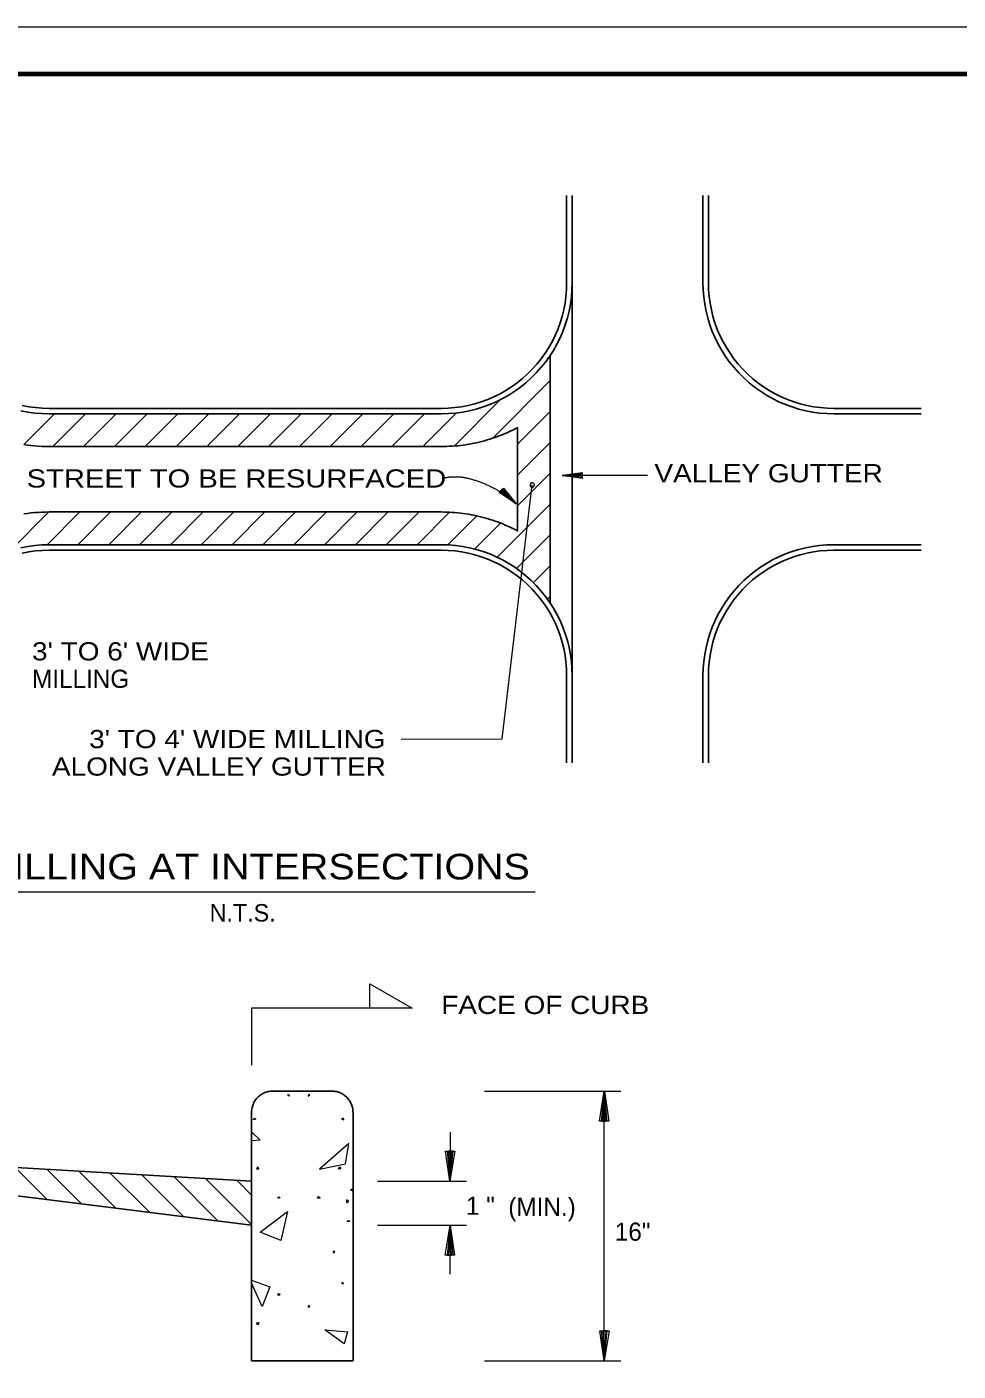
# Model space of a CAD drawing. Extents: x 44.6 to 61.6, y -38.7 to -27.7.
# Drawn here: x 50.34 to 54.61, y -33.85 to -27.69 of the extents above; entities that cross this region are included whole.
import ezdxf

# ---------------------------------------------------------------- set-up
doc = ezdxf.new("R2010")
doc.units = 0
doc.header["$LTSCALE"] = 0.025
doc.layers.add('10', color=7, linetype='Continuous')
for name, color, linetype, lineweight in [('6', 7, 'Continuous', 13), ('60', 7, 'Continuous', 13), ('8', 7, 'Continuous', 13), ('9', 7, 'Continuous', 13)]:
    doc.layers.add(name, color=color, linetype=linetype, lineweight=lineweight)

msp = doc.modelspace()

# ---------------------------------------------------------------- linework, layer by layer
at = {"layer": '6', "lineweight": 25}
for p, q in [((52.8405, -30.66542), (52.8405, -28.86542)), ((52.7405, -30.33375), (52.7405, -29.19707))]:
    msp.add_line(p, q, dxfattribs=at)
at = {"layer": '6'}
for p, q in [((52.7405, -29.31338), (52.47658, -29.57729)), ((52.29935, -29.6131), (52.51196, -29.40049)), ((50.32615, -29.60641), (50.46714, -29.46542)), ((50.60856, -29.46542), (50.45856, -29.61542)), ((50.59998, -29.61542), (50.74998, -29.46542)), ((50.89141, -29.46542), (50.74141, -29.61542)), ((50.88282, -29.61542), (51.03282, -29.46542)), ((51.17425, -29.46542), (51.02425, -29.61542)), ((51.16567, -29.61542), (51.31567, -29.46542)), ((51.45708, -29.46542), (51.30708, -29.61542)), ((51.44851, -29.61542), (51.59851, -29.46542)), ((51.73993, -29.46542), (51.58993, -29.61542)), ((51.73135, -29.61542), (51.88135, -29.46542)), ((52.02277, -29.46542), (51.87277, -29.61542)), ((52.0142, -29.61542), (52.1642, -29.46542)), ((52.30961, -29.46142), (52.15561, -29.61542)), ((52.5905, -29.60479), (52.7405, -29.45479)), ((52.7405, -29.59622), (52.5905, -29.74622)), ((52.5905, -29.88764), (52.7405, -29.73764)), ((53.18669, -29.74781), (52.79539, -29.74781)), ((52.7405, -29.87906), (52.4967, -30.12286)), ((50.44172, -29.91509), (50.26455, -30.09226)), ((50.43275, -30.06549), (50.58282, -29.91542)), ((50.72425, -29.91542), (50.57425, -30.06542)), ((50.71567, -30.06542), (50.86567, -29.91542)), ((51.00708, -29.91542), (50.85708, -30.06542)), ((50.99851, -30.06542), (51.14851, -29.91542)), ((51.28993, -29.91542), (51.13993, -30.06542)), ((51.28135, -30.06542), (51.43135, -29.91542)), ((51.57277, -29.91542), (51.42277, -30.06542)), ((51.5642, -30.06542), (51.7142, -29.91542)), ((51.85561, -29.91542), (51.70561, -30.06542)), ((51.84704, -30.06542), (51.99704, -29.91542)), ((52.13846, -29.91542), (51.98846, -30.06542)), ((52.12989, -30.06542), (52.2789, -29.9164)), ((52.4034, -29.93332), (52.27055, -30.06617)), ((52.39301, -30.08512), (52.5119, -29.96624)), ((52.58606, -30.17492), (52.7405, -30.02048)), ((52.7405, -30.16191), (52.663, -30.2394)), ((52.72807, -30.31575), (52.7405, -30.30332)), ((52.43949, -32.56991), (53.06341, -32.56991)), ((52.98778, -33.80639), (52.98778, -32.56991)), ((52.28068, -32.75897), (52.28068, -32.98332)), ((50.2867, -32.9203), (50.43543, -33.06778)), ((50.59172, -33.08795), (50.43291, -32.92914)), ((50.57786, -32.9367), (50.74801, -33.10684)), ((50.9043, -33.12701), (50.7228, -32.94551)), ((50.86776, -32.95434), (51.06059, -33.14593)), ((51.21689, -33.16609), (51.01397, -32.96191)), ((51.15891, -32.97072), (51.37193, -33.18374)), ((51.37066, -33.04634), (51.30386, -32.97955)), ((51.94793, -32.98332), (52.3563, -32.98332)), ((51.94793, -33.18499), (52.3563, -33.18499)), ((52.28068, -33.40934), (52.28068, -33.18499)), ((52.43949, -33.80639), (53.06341, -33.80639))]:
    msp.add_line(p, q, dxfattribs=at)
at = {"layer": '6', "lineweight": 25}
for points in [[(52.8405, -28.46542), (52.8405, -28.86542), (52.83961, -28.8979), (52.83698, -28.93028), (52.83259, -28.96248), (52.82647, -28.9944), (52.81862, -29.02593), (52.80909, -29.057), (52.79789, -29.0875), (52.78504, -29.11734), (52.7706, -29.14646), (52.75461, -29.17475), (52.73711, -29.20212), (52.71816, -29.22852), (52.69779, -29.25384), (52.67609, -29.27803), (52.65311, -29.30101), (52.62893, -29.32271), (52.6036, -29.34307), (52.57721, -29.36203), (52.54983, -29.37953), (52.52154, -29.39552), (52.49244, -29.40996), (52.46258, -29.4228), (52.43208, -29.43401), (52.40102, -29.44354), (52.36948, -29.45139), (52.33757, -29.45751), (52.30537, -29.4619), (52.27298, -29.46454), (52.2405, -29.46542), (52.2405, -29.46542), (50.44203, -29.46542), (50.40955, -29.46453), (50.37717, -29.4619), (50.34497, -29.45751), (50.31305, -29.45139)], [(50.31843, -29.42697), (50.34901, -29.43284), (50.37986, -29.43704), (50.4109, -29.43957), (50.44203, -29.44042), (50.44203, -29.44042), (52.2405, -29.44042), (52.27163, -29.43957), (52.30267, -29.43704), (52.33352, -29.43284), (52.3641, -29.42697), (52.39432, -29.41946), (52.42409, -29.41031), (52.45332, -29.39957), (52.48194, -29.38727), (52.50983, -29.37344), (52.53694, -29.3581), (52.56318, -29.34133), (52.58847, -29.32317), (52.61275, -29.30366), (52.63593, -29.28286), (52.65795, -29.26084), (52.67874, -29.23767), (52.69825, -29.2134), (52.71642, -29.18809), (52.73319, -29.16186), (52.74852, -29.13475), (52.76235, -29.10685), (52.77466, -29.07825), (52.7854, -29.04901), (52.79454, -29.01925), (52.80205, -28.98902), (52.80793, -28.95844), (52.81213, -28.92758), (52.81466, -28.89654), (52.8155, -28.86542), (52.8155, -28.86542), (52.8155, -28.46542)], [(54.4405, -29.46542), (54.0405, -29.46542), (54.00801, -29.46453), (53.97563, -29.4619), (53.94343, -29.45751), (53.91152, -29.45139), (53.87998, -29.44354), (53.84892, -29.43401), (53.81842, -29.4228), (53.78856, -29.40996), (53.75946, -29.39552), (53.73117, -29.37953), (53.70379, -29.36203), (53.6774, -29.34307), (53.65206, -29.32271), (53.62787, -29.30101), (53.60491, -29.27803), (53.5832, -29.25384), (53.56284, -29.22852), (53.54389, -29.20212), (53.52639, -29.17475), (53.5104, -29.14646), (53.49596, -29.11735), (53.48311, -29.0875), (53.47191, -29.057), (53.46236, -29.02594), (53.45453, -28.9944), (53.44841, -28.96249), (53.44402, -28.93029), (53.44138, -28.8979), (53.4405, -28.86542), (53.4405, -28.86542), (53.4405, -28.46542)], [(53.4655, -28.46542), (53.4655, -28.86542), (53.46634, -28.89654), (53.46886, -28.92758), (53.47307, -28.95844), (53.47894, -28.98902), (53.48646, -29.01924), (53.49559, -29.04901), (53.50633, -29.07824), (53.51865, -29.10685), (53.53248, -29.13475), (53.5478, -29.16185), (53.56457, -29.18809), (53.58275, -29.2134), (53.60225, -29.23767), (53.62305, -29.26084), (53.64507, -29.28286), (53.66825, -29.30366), (53.69252, -29.32317), (53.71781, -29.34133), (53.74405, -29.3581), (53.77117, -29.37344), (53.79906, -29.38727), (53.82767, -29.39957), (53.8569, -29.41031), (53.88667, -29.41946), (53.9169, -29.42697), (53.94748, -29.43284), (53.97833, -29.43704), (54.00936, -29.43957), (54.0405, -29.44042), (54.0405, -29.44042), (54.4405, -29.44042)], [(50.326, -29.60639), (50.34247, -29.60878), (50.35899, -29.6108), (50.37555, -29.61247), (50.39215, -29.61376), (50.40876, -29.61468), (50.42539, -29.61523), (50.44203, -29.61542), (52.2405, -29.61542), (52.25305, -29.61531), (52.2656, -29.61499), (52.27816, -29.61447), (52.29069, -29.61373), (52.30321, -29.61279), (52.31571, -29.61164), (52.3282, -29.61027), (52.34065, -29.6087), (52.35308, -29.60692), (52.36548, -29.60493), (52.37784, -29.60273), (52.39017, -29.60033), (52.40245, -29.59772), (52.41469, -29.59491), (52.42687, -29.59189), (52.43901, -29.58867), (52.45109, -29.58524), (52.46311, -29.58161), (52.47507, -29.57779), (52.48696, -29.57376), (52.49879, -29.56954), (52.51054, -29.56511), (52.52222, -29.5605), (52.53381, -29.55568), (52.54532, -29.55068), (52.55676, -29.54548), (52.56809, -29.54008), (52.57934, -29.53451), (52.5905, -29.52874), (52.5905, -29.52874), (52.5905, -30.00209), (52.57934, -29.99632), (52.56809, -29.99074), (52.55675, -29.98535), (52.54532, -29.98016), (52.53381, -29.97515), (52.52222, -29.97033), (52.51054, -29.96572), (52.49878, -29.96129), (52.48696, -29.95707), (52.47507, -29.95304), (52.46311, -29.94922), (52.45109, -29.94558), (52.43901, -29.94217), (52.42687, -29.93894), (52.41469, -29.93593), (52.40245, -29.93311), (52.39017, -29.9305), (52.37784, -29.92809), (52.36548, -29.92591), (52.35308, -29.92392), (52.34065, -29.92214), (52.3282, -29.92056), (52.31571, -29.9192), (52.30321, -29.91804), (52.29069, -29.91709), (52.27816, -29.91636), (52.2656, -29.91583), (52.25305, -29.91552), (52.2405, -29.91542), (50.44203, -29.91542), (50.4254, -29.9156), (50.40876, -29.91616), (50.39215, -29.91707), (50.37555, -29.91836), (50.35899, -29.92003), (50.34247, -29.92205), (50.326, -29.92445)], [(50.31305, -30.07945), (50.34496, -30.07332), (50.37716, -30.06894), (50.40955, -30.06629), (50.44203, -30.06542), (52.2405, -30.06542), (52.27298, -30.06629), (52.30537, -30.06893), (52.33757, -30.07332), (52.36948, -30.07944), (52.40102, -30.08728), (52.43208, -30.09682), (52.46258, -30.10803), (52.49244, -30.12086), (52.52154, -30.13531), (52.54983, -30.1513), (52.57721, -30.1688), (52.6036, -30.18776), (52.62893, -30.20811), (52.65311, -30.22982), (52.67609, -30.25279), (52.69779, -30.27698), (52.71816, -30.30231), (52.73711, -30.32871), (52.75461, -30.35608), (52.7706, -30.38437), (52.78504, -30.41348), (52.79789, -30.44333), (52.80909, -30.47383), (52.81862, -30.5049), (52.82647, -30.53644), (52.83259, -30.56834), (52.83698, -30.60054), (52.83961, -30.63294), (52.8405, -30.66542), (52.8405, -30.66542), (52.8405, -31.06542)], [(53.4405, -31.06542), (53.4405, -30.66542), (53.44138, -30.63293), (53.44402, -30.60054), (53.44841, -30.56834), (53.45453, -30.53644), (53.46236, -30.5049), (53.47191, -30.47383), (53.48311, -30.44333), (53.49596, -30.41348), (53.5104, -30.38437), (53.52639, -30.35608), (53.54389, -30.3287), (53.56284, -30.30231), (53.5832, -30.27698), (53.60491, -30.25279), (53.62787, -30.22982), (53.65206, -30.20811), (53.6774, -30.18776), (53.70379, -30.1688), (53.73117, -30.1513), (53.75946, -30.13531), (53.78856, -30.12087), (53.81842, -30.10803), (53.84892, -30.09682), (53.87998, -30.08728), (53.91152, -30.07945), (53.94343, -30.07332), (53.97563, -30.06894), (54.00802, -30.06629), (54.0405, -30.06542), (54.4405, -30.06542)], [(52.8155, -31.06542), (52.8155, -30.66542), (52.81466, -30.63428), (52.81213, -30.60325), (52.80793, -30.57239), (52.80205, -30.5418), (52.79454, -30.51158), (52.7854, -30.48181), (52.77466, -30.45258), (52.76235, -30.42398), (52.74852, -30.39608), (52.73319, -30.36897), (52.71642, -30.34273), (52.69825, -30.31744), (52.67874, -30.29317), (52.65795, -30.26999), (52.63593, -30.24797), (52.61275, -30.22718), (52.58847, -30.20767), (52.56318, -30.1895), (52.53694, -30.17272), (52.50983, -30.1574), (52.48194, -30.14356), (52.45332, -30.13125), (52.42409, -30.12052), (52.39432, -30.11137), (52.3641, -30.10386), (52.33352, -30.09799), (52.30267, -30.09379), (52.27163, -30.09126), (52.2405, -30.09042), (52.2405, -30.09042), (50.44203, -30.09042), (50.41091, -30.09126), (50.37986, -30.09378), (50.34901, -30.09799), (50.31843, -30.10385)], [(54.4405, -30.09042), (54.0405, -30.09042), (54.00936, -30.09126), (53.97833, -30.09378), (53.94747, -30.09799), (53.91689, -30.10385), (53.88667, -30.11137), (53.8569, -30.12051), (53.82767, -30.13125), (53.79906, -30.14356), (53.77117, -30.1574), (53.74405, -30.17272), (53.71781, -30.18949), (53.69252, -30.20767), (53.66825, -30.22718), (53.64507, -30.24797), (53.62305, -30.26999), (53.60225, -30.29317), (53.58275, -30.31744), (53.56457, -30.34273), (53.5478, -30.36897), (53.53248, -30.39608), (53.51865, -30.42398), (53.50633, -30.45258), (53.49559, -30.48182), (53.48646, -30.51158), (53.47894, -30.54181), (53.47307, -30.5724), (53.46886, -30.60325), (53.46634, -30.63429), (53.4655, -30.66542), (53.4655, -31.06542)], [(51.7387, -32.56991), (51.46772, -32.56991), (51.46768, -32.56984), (51.46244, -32.56999), (51.45721, -32.57042), (51.45202, -32.57113), (51.44686, -32.57211), (51.44178, -32.57337), (51.43677, -32.57492), (51.43184, -32.57672), (51.42703, -32.57879), (51.42233, -32.58113), (51.41777, -32.58371), (51.41335, -32.58653), (51.40909, -32.58958), (51.40501, -32.59287), (51.4011, -32.59638), (51.3974, -32.60008), (51.3939, -32.60398), (51.39061, -32.60806), (51.38755, -32.61232), (51.38473, -32.61674), (51.38216, -32.6213), (51.37982, -32.626), (51.37775, -32.63082), (51.37595, -32.63574), (51.37441, -32.64075), (51.37314, -32.64583), (51.37216, -32.65099), (51.37145, -32.65618), (51.37102, -32.66141), (51.37087, -32.66665), (51.37087, -32.66665), (51.37066, -32.66697), (51.37066, -33.80639), (51.83576, -33.80639), (51.83576, -32.66697), (51.83552, -32.66665), (51.83537, -32.66141), (51.83495, -32.65618), (51.83424, -32.65099), (51.83325, -32.64583), (51.83199, -32.64075), (51.83045, -32.63574), (51.82865, -32.63082), (51.82657, -32.626), (51.82424, -32.6213), (51.82166, -32.61674), (51.81883, -32.61232), (51.81578, -32.60806), (51.81249, -32.60398), (51.80899, -32.60008), (51.80528, -32.59638), (51.80139, -32.59287), (51.7973, -32.58958), (51.79304, -32.58653), (51.78862, -32.58371), (51.78406, -32.58113), (51.77936, -32.57879), (51.77454, -32.57672), (51.76962, -32.57492), (51.76461, -32.57337), (51.75952, -32.57211), (51.75437, -32.57113), (51.74919, -32.57042), (51.74396, -32.56999), (51.73872, -32.56984), (51.73872, -32.56984)]]:
    msp.add_lwpolyline(points, dxfattribs=at)
at = {"layer": '6'}
for points in [[(52.24596, -29.7608), (52.24795, -29.76031), (52.24994, -29.75984), (52.25194, -29.7594), (52.25394, -29.75896), (52.25594, -29.75854), (52.25794, -29.75815), (52.25995, -29.75776), (52.26196, -29.7574), (52.26398, -29.75704), (52.26599, -29.75671), (52.26801, -29.7564), (52.27003, -29.75609), (52.27206, -29.75581), (52.27409, -29.75555), (52.27611, -29.7553), (52.27815, -29.75507), (52.28019, -29.75485), (52.28222, -29.75466), (52.28426, -29.75448), (52.28629, -29.75431), (52.28833, -29.75417), (52.29037, -29.75404), (52.29242, -29.75393), (52.29446, -29.75383), (52.2965, -29.75376), (52.29855, -29.7537), (52.30059, -29.75366), (52.30264, -29.75362), (52.30468, -29.75362), (52.30673, -29.75362), (52.30877, -29.75366), (52.31081, -29.7537), (52.31286, -29.75376), (52.31491, -29.75383), (52.31695, -29.75393), (52.31899, -29.75404), (52.32103, -29.75417), (52.32307, -29.75431), (52.3251, -29.75448), (52.32715, -29.75466), (52.32918, -29.75485), (52.33122, -29.75507), (52.33325, -29.7553), (52.33527, -29.75555), (52.3373, -29.75581), (52.33933, -29.75609), (52.34135, -29.7564), (52.34338, -29.75671), (52.34539, -29.75704), (52.34741, -29.7574), (52.34942, -29.75776), (52.35143, -29.75815), (52.35343, -29.75854), (52.35543, -29.75896), (52.35743, -29.7594), (52.35943, -29.75984), (52.36142, -29.76031), (52.36341, -29.7608), (52.36761, -29.76186), (52.37182, -29.76297), (52.37602, -29.7641), (52.3802, -29.76527), (52.38437, -29.76648), (52.38854, -29.76772), (52.3927, -29.76899), (52.39684, -29.7703), (52.40098, -29.77165), (52.40509, -29.77302), (52.40921, -29.77444), (52.4133, -29.77589), (52.41739, -29.77736), (52.42146, -29.77889), (52.42552, -29.78044), (52.42957, -29.78202), (52.4336, -29.78365), (52.43762, -29.78529), (52.44162, -29.78698), (52.44561, -29.7887), (52.44959, -29.79046), (52.45355, -29.79224), (52.4575, -29.79406), (52.46144, -29.79592), (52.46535, -29.7978), (52.46925, -29.79972), (52.47314, -29.80167), (52.477, -29.80366), (52.48085, -29.80567), (52.48469, -29.80772), (52.4885, -29.80979), (52.4923, -29.81191), (52.49608, -29.81405), (52.49984, -29.81623), (52.50358, -29.81844), (52.50731, -29.82068), (52.51102, -29.82295), (52.51471, -29.82524), (52.51837, -29.82757), (52.52202, -29.82994), (52.52565, -29.83233), (52.52926, -29.83475)], [(52.05694, -30.95607), (52.52047, -30.95509), (52.65744, -29.79157)], [(52.52926, -29.83475), (52.53284, -29.83721), (52.53641, -29.83969), (52.53996, -29.84221), (52.54348, -29.84475), (52.54698, -29.84732), (52.55047, -29.84992), (52.55393, -29.85255), (52.55736, -29.85521), (52.56078, -29.8579), (52.56417, -29.86061), (52.56754, -29.86336), (52.57089, -29.86614), (52.57421, -29.86894), (52.57751, -29.87176), (52.58078, -29.87462), (52.58403, -29.87751)], [(52.10674, -32.19016), (51.37066, -32.19016), (51.37066, -32.4507)], [(51.37066, -32.75645), (51.40974, -32.79426), (51.37066, -32.79805)], [(51.37066, -33.43707), (51.45384, -33.46732), (51.41982, -33.55807), (51.37066, -33.44968)]]:
    msp.add_lwpolyline(points, dxfattribs=at)
for points in [[(52.66083, -29.78217), (52.65979, -29.78185), (52.65873, -29.78166), (52.65765, -29.78157), (52.65656, -29.78161), (52.6555, -29.78176), (52.65445, -29.78203), (52.65343, -29.78241), (52.65247, -29.7829), (52.65155, -29.78349), (52.65072, -29.78417), (52.64996, -29.78494), (52.64928, -29.78578), (52.64871, -29.7867), (52.64823, -29.78768), (52.64786, -29.7887), (52.6476, -29.78975), (52.64747, -29.79082), (52.64744, -29.79191), (52.64753, -29.79298), (52.64775, -29.79404), (52.64807, -29.79507), (52.6485, -29.79606), (52.64904, -29.79701), (52.64968, -29.79789), (52.65041, -29.79869), (52.65122, -29.79941), (52.6521, -29.80003), (52.65304, -29.80055), (52.65404, -29.80098), (52.65404, -29.80098), (52.65508, -29.80129), (52.65615, -29.80149), (52.65722, -29.80157), (52.6583, -29.80153), (52.65937, -29.80139), (52.66043, -29.80111), (52.66144, -29.80074), (52.66241, -29.80025), (52.66331, -29.79966), (52.66416, -29.79898), (52.66492, -29.79821), (52.66559, -29.79736), (52.66617, -29.79645), (52.66665, -29.79547), (52.66701, -29.79446), (52.66727, -29.7934), (52.66741, -29.79232), (52.66743, -29.79124), (52.66733, -29.79017), (52.66712, -29.7891), (52.6668, -29.78807), (52.66636, -29.78708), (52.66583, -29.78614), (52.6652, -29.78526), (52.66447, -29.78446), (52.66366, -29.78374), (52.66277, -29.78311), (52.66183, -29.78259), (52.66083, -29.78217)], [(52.10674, -32.19016), (51.9124, -32.19016), (51.9124, -32.07868)], [(51.53578, -32.58755), (51.54207, -32.58503), (51.54334, -32.59259)], [(51.63786, -32.58755), (51.63157, -32.58503), (51.6303, -32.59259)], [(51.37949, -32.70099), (51.38326, -32.69343), (51.39082, -32.69722)], [(51.79416, -32.70099), (51.79039, -32.69343), (51.78282, -32.69722)], [(51.68199, -32.92786), (51.80172, -32.90393), (51.81684, -32.81066)], [(51.39334, -32.92661), (51.4047, -32.92786), (51.39966, -32.91778)], [(51.7803, -32.92661), (51.76895, -32.92786), (51.77399, -32.91778)], [(51.83197, -33.02618), (51.83072, -33.01861), (51.82441, -33.02366)], [(51.48914, -33.06022), (51.49545, -33.05518), (51.50174, -33.05895)], [(51.68451, -33.06022), (51.6782, -33.05518), (51.67191, -33.05895)], [(51.80551, -33.08164), (51.81684, -33.07534), (51.80551, -33.06903)], [(51.40974, -33.21651), (51.53578, -33.12197), (51.50426, -33.25557)], [(51.82064, -33.16609), (51.81307, -33.16482), (51.80676, -33.16734)], [(51.75257, -33.30599), (51.74501, -33.30474), (51.74626, -33.3123)], [(51.79291, -33.45347), (51.78911, -33.44716), (51.78282, -33.45095)], [(51.48914, -33.50009), (51.49545, -33.50514), (51.50174, -33.50136)], [(51.63786, -33.55555), (51.63157, -33.55303), (51.6303, -33.56059)], [(51.39334, -33.63245), (51.4047, -33.63118), (51.39966, -33.64253)], [(51.7072, -33.66395), (51.81055, -33.67403), (51.79543, -33.72824)]]:
    msp.add_lwpolyline(points, close=True, dxfattribs=at)
at = {"layer": '6', "lineweight": 25}
msp.add_lwpolyline([(51.37066, -32.98332), (48.36457, -32.80939), (51.37066, -33.18499)], close=True, dxfattribs=at)
at = {"layer": '60'}
msp.add_lwpolyline([(61.57033, -38.69864), (44.55984, -38.69864), (44.55984, -27.69184), (61.57033, -27.69184)], close=True, dxfattribs=at)
at = {"layer": '60', "lineweight": 70}
msp.add_lwpolyline([(60.8892, -27.90872), (44.82119, -27.90872), (44.82119, -38.46427), (60.8892, -38.46427)], close=True, dxfattribs=at)
at = {"layer": '8'}
msp.add_line((50.11106, -31.65631), (52.67071, -31.65631), dxfattribs=at)
at = {"layer": '9'}
for points in [[(52.8869, -29.73867), (52.79539, -29.74781), (52.8869, -29.74781), (52.8869, -29.75239), (52.79539, -29.74781), (52.8869, -29.75696), (52.8869, -29.74324), (52.79997, -29.74781)], [(52.79584, -29.74722), (52.88697, -29.73412), (52.88697, -29.76246), (52.79553, -29.74754)], [(52.58329, -29.87765), (52.50665, -29.82665), (52.52554, -29.80553), (52.58374, -29.87761)], [(52.50973, -29.82331), (52.58403, -29.87751), (52.51583, -29.8165), (52.51888, -29.81309), (52.58403, -29.87751), (52.52193, -29.80968), (52.51278, -29.81991), (52.58061, -29.87446)], [(52.98867, -32.57059), (53.00831, -32.70728), (52.96581, -32.70728), (52.98819, -32.57012)], [(53.0015, -32.70718), (52.98778, -32.56991), (52.98778, -32.70718), (52.98092, -32.70718), (52.98778, -32.56991), (52.97406, -32.70718), (52.99464, -32.70718), (52.98778, -32.57678)], [(52.27978, -32.98264), (52.26015, -32.84595), (52.30265, -32.84595), (52.28027, -32.9831)], [(52.26696, -32.84606), (52.28068, -32.98332), (52.28068, -32.84606), (52.28753, -32.84606), (52.28068, -32.98332), (52.2944, -32.84606), (52.27381, -32.84606), (52.28068, -32.97645)], [(52.28156, -33.18568), (52.30121, -33.32236), (52.25871, -33.32236), (52.28108, -33.18521)], [(52.2944, -33.32226), (52.28068, -33.18499), (52.28068, -33.32226), (52.27381, -33.32226), (52.28068, -33.18499), (52.26696, -33.32226), (52.28753, -33.32226), (52.28068, -33.19186)], [(52.98689, -33.8057), (52.96725, -33.66901), (53.00975, -33.66901), (52.98738, -33.80617)], [(52.97406, -33.66913), (52.98778, -33.80639), (52.98778, -33.66913), (52.99464, -33.66913), (52.98778, -33.80639), (53.0015, -33.66913), (52.98092, -33.66913), (52.98778, -33.79951)]]:
    msp.add_lwpolyline(points, dxfattribs=at)

# ---------------------------------------------------------------- texts
at = {"layer": '10'}
msp.add_text('N.T.S.', height=0.08, dxfattribs=at).set_placement((51.17813, -31.79274))
at = {"layer": '6'}
for s, width, p in [('VALLEY GUTTER', 1.15, (53.21818, -29.77931)), ('STREET TO BE RESURFACED', 1.2, (50.33918, -29.80341)), ("3' TO 6' WIDE", 1.15, (50.36392, -30.59584)), ("3' TO 4' WIDE MILLING", 1.15, (50.62585, -30.99796)), ('ALONG VALLEY GUTTER', 1.15, (50.45528, -31.12394)), ('FACE OF CURB', 1.15, (52.24034, -32.21664))]:
    msp.add_text(s, height=0.08333, dxfattribs=dict(at, width=width)).set_placement(p)
for s, p in [('MILLING', (50.36392, -30.72183)), ('1 "', (52.35378, -33.13709)), ('(MIN.)', (52.54796, -33.14245)), ('16"', (53.03617, -33.25609))]:
    msp.add_text(s, height=0.08333, dxfattribs=at).set_placement(p)
at = {"layer": '8', "width": 1.15}
msp.add_text('MILLING AT INTERSECTIONS', height=0.1175, dxfattribs=at).set_placement((50.12656, -31.59983))

doc.saveas('drawing.dxf')
